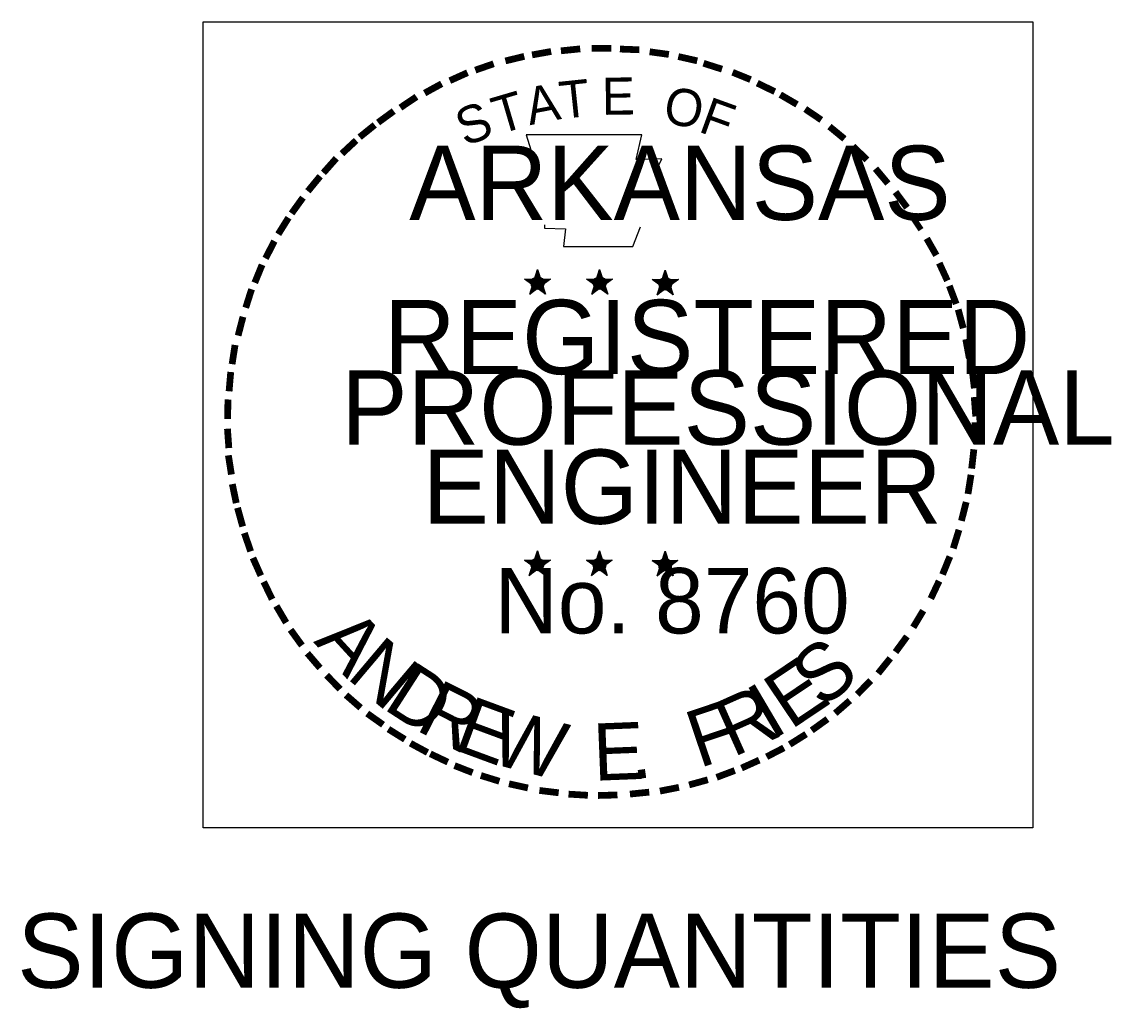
# Model space of a CAD drawing. Extents: x 1226613 to 1228135, y 151309 to 152326.
# Drawn here: x 1227951.4 to 1228134.6, y 151309.4 to 151475.4 of the extents above; entities that cross this region are included whole.
import ezdxf

# ---------------------------------------------------------------- set-up
doc = ezdxf.new("R2010")
doc.units = 0
for name, color, linetype in [('R_Border Notes', 7, 'Continuous'), ('R_Border PE', 7, 'Continuous'), ('R_Border Prem', 7, 'Continuous')]:
    doc.layers.add(name, color=color, linetype=linetype)

msp = doc.modelspace()

# ---------------------------------------------------------------- linework, layer by layer
at = {"layer": 'R_Border PE'}
for p, q in [((1228038.16, 151433.71), (1228037.85, 151432.15)), ((1228038.16, 151433.71), (1228037.91, 151432.09)), ((1228038.16, 151433.71), (1228038.1, 151432.15)), ((1228038.16, 151431.4), (1228038.16, 151433.71)), ((1228038.16, 151433.71), (1228038.6, 151432.09)), ((1228038.16, 151433.71), (1228038.47, 151432.15)), ((1228038.16, 151433.71), (1228038.35, 151432.15)), ((1228048.6, 151433.71), (1228048.28, 151432.15)), ((1228048.6, 151433.71), (1228048.35, 151432.09)), ((1228048.6, 151433.71), (1228048.47, 151432.15)), ((1228048.6, 151431.4), (1228048.6, 151433.71)), ((1228048.6, 151433.71), (1228049.03, 151432.09)), ((1228048.6, 151433.71), (1228048.91, 151432.15)), ((1228048.6, 151433.71), (1228048.72, 151432.15)), ((1228059.66, 151433.59), (1228059.28, 151432.09)), ((1228059.66, 151433.59), (1228059.41, 151432.03)), ((1228059.66, 151433.59), (1228059.53, 151432.03)), ((1228059.66, 151431.34), (1228059.66, 151433.59)), ((1228059.66, 151433.59), (1228060.1, 151432.03)), ((1228059.66, 151433.59), (1228059.97, 151432.03)), ((1228059.66, 151433.59), (1228059.78, 151432.09)), ((1228035.97, 151432.09), (1228038.16, 151431.4)), ((1228035.97, 151432.09), (1228037.6, 151431.96)), ((1228035.97, 151432.09), (1228037.6, 151431.84)), ((1228035.97, 151432.09), (1228037.53, 151431.71)), ((1228035.97, 151432.09), (1228037.53, 151431.46)), ((1228035.97, 151432.09), (1228037.47, 151431.34)), ((1228035.97, 151432.09), (1228037.47, 151431.21)), ((1228036.85, 151429.53), (1228038.16, 151431.4)), ((1228036.85, 151429.53), (1228037.53, 151431.28)), ((1228036.85, 151429.53), (1228037.6, 151431.09)), ((1228036.85, 151429.53), (1228037.72, 151431.03)), ((1228036.85, 151429.53), (1228038.16, 151430.9)), ((1228036.85, 151429.53), (1228037.91, 151430.84)), ((1228036.85, 151429.53), (1228038.22, 151430.71)), ((1228040.35, 151432.09), (1228038.16, 151431.4)), ((1228039.53, 151429.53), (1228038.16, 151431.4)), ((1228039.53, 151429.53), (1228038.16, 151430.9)), ((1228039.53, 151429.53), (1228038.16, 151430.71)), ((1228040.35, 151432.09), (1228038.41, 151431.96)), ((1228039.53, 151429.53), (1228038.41, 151430.84)), ((1228040.35, 151432.09), (1228038.53, 151431.78)), ((1228040.35, 151432.09), (1228038.53, 151431.65)), ((1228039.53, 151429.53), (1228038.6, 151431.09)), ((1228039.53, 151429.53), (1228038.66, 151431.34)), ((1228039.53, 151429.53), (1228038.78, 151431.4)), ((1228040.35, 151432.09), (1228038.97, 151431.53)), ((1228040.35, 151432.09), (1228039.1, 151431.46)), ((1228040.35, 151432.09), (1228039.16, 151431.4)), ((1228046.41, 151432.09), (1228048.6, 151431.4)), ((1228046.41, 151432.09), (1228048.03, 151431.96)), ((1228046.41, 151432.09), (1228048.03, 151431.84)), ((1228046.41, 151432.09), (1228047.97, 151431.71)), ((1228046.41, 151432.09), (1228047.91, 151431.46)), ((1228046.41, 151432.09), (1228047.91, 151431.34)), ((1228046.41, 151432.09), (1228047.91, 151431.21)), ((1228047.28, 151429.53), (1228048.6, 151431.4)), ((1228047.28, 151429.53), (1228047.97, 151431.28)), ((1228047.28, 151429.53), (1228048.03, 151431.09)), ((1228047.28, 151429.53), (1228048.16, 151431.03)), ((1228047.28, 151429.53), (1228048.6, 151430.9)), ((1228047.28, 151429.53), (1228048.35, 151430.84)), ((1228047.28, 151429.53), (1228048.66, 151430.71)), ((1228050.78, 151432.09), (1228048.6, 151431.4)), ((1228049.97, 151429.53), (1228048.6, 151431.4)), ((1228049.97, 151429.53), (1228048.6, 151430.9)), ((1228049.97, 151429.53), (1228048.6, 151430.71)), ((1228050.78, 151432.09), (1228048.85, 151431.96)), ((1228049.97, 151429.53), (1228048.85, 151430.84)), ((1228050.78, 151432.09), (1228048.97, 151431.78)), ((1228050.78, 151432.09), (1228048.97, 151431.65)), ((1228049.97, 151429.53), (1228049.03, 151431.09)), ((1228049.97, 151429.53), (1228049.1, 151431.34)), ((1228049.97, 151429.53), (1228049.22, 151431.4)), ((1228050.78, 151432.09), (1228049.41, 151431.53)), ((1228050.78, 151432.09), (1228049.53, 151431.46)), ((1228050.78, 151432.09), (1228049.6, 151431.4)), ((1228057.47, 151432.03), (1228059.66, 151431.34)), ((1228057.47, 151432.03), (1228059.1, 151431.84)), ((1228057.47, 151432.03), (1228059.03, 151431.71)), ((1228057.47, 151432.03), (1228059.03, 151431.65)), ((1228057.47, 151432.03), (1228058.97, 151431.4)), ((1228057.47, 151432.03), (1228058.97, 151431.28)), ((1228057.47, 151432.03), (1228058.97, 151431.15)), ((1228058.28, 151429.46), (1228059.66, 151431.34)), ((1228058.28, 151429.46), (1228059.03, 151431.21)), ((1228058.28, 151429.46), (1228059.1, 151431.03)), ((1228058.28, 151429.46), (1228059.22, 151430.96)), ((1228058.28, 151429.46), (1228059.66, 151430.84)), ((1228058.28, 151429.46), (1228059.41, 151430.78)), ((1228058.28, 151429.46), (1228059.72, 151430.65)), ((1228061.85, 151432.03), (1228059.66, 151431.34)), ((1228060.97, 151429.46), (1228059.66, 151431.34)), ((1228060.97, 151429.46), (1228059.66, 151430.84)), ((1228060.97, 151429.46), (1228059.66, 151430.65)), ((1228061.85, 151432.03), (1228059.91, 151431.9)), ((1228060.97, 151429.46), (1228059.91, 151430.78)), ((1228061.85, 151432.03), (1228060.03, 151431.71)), ((1228061.85, 151432.03), (1228060.03, 151431.59)), ((1228060.97, 151429.46), (1228060.1, 151431.03)), ((1228060.97, 151429.46), (1228060.16, 151431.28)), ((1228060.97, 151429.46), (1228060.28, 151431.28)), ((1228061.85, 151432.03), (1228060.47, 151431.46)), ((1228061.85, 151432.03), (1228060.53, 151431.4)), ((1228061.85, 151432.03), (1228060.66, 151431.34)), ((1228038.16, 151386.34), (1228037.78, 151384.84)), ((1228038.16, 151386.34), (1228037.91, 151384.78)), ((1228038.16, 151386.34), (1228038.03, 151384.78)), ((1228038.16, 151384.09), (1228038.16, 151386.34)), ((1228038.16, 151386.34), (1228038.6, 151384.78)), ((1228038.16, 151386.34), (1228038.47, 151384.78)), ((1228038.16, 151386.34), (1228038.28, 151384.78)), ((1228048.6, 151386.34), (1228048.22, 151384.84)), ((1228048.6, 151386.34), (1228048.35, 151384.78)), ((1228048.6, 151386.34), (1228048.47, 151384.78)), ((1228048.6, 151384.09), (1228048.6, 151386.34)), ((1228048.6, 151386.34), (1228048.97, 151384.78)), ((1228048.6, 151386.34), (1228048.91, 151384.78)), ((1228048.6, 151386.34), (1228048.72, 151384.78)), ((1228035.97, 151384.78), (1228038.16, 151384.09)), ((1228035.97, 151384.78), (1228037.6, 151384.59)), ((1228035.97, 151384.78), (1228037.53, 151384.46)), ((1228035.97, 151384.78), (1228037.53, 151384.4)), ((1228035.97, 151384.78), (1228037.47, 151384.15)), ((1228035.97, 151384.78), (1228037.47, 151384.03)), ((1228035.97, 151384.78), (1228037.47, 151383.9)), ((1228040.35, 151384.78), (1228038.16, 151384.09)), ((1228040.35, 151384.78), (1228038.41, 151384.65)), ((1228040.35, 151384.78), (1228038.53, 151384.46)), ((1228040.35, 151384.78), (1228038.53, 151384.34)), ((1228040.35, 151384.78), (1228038.91, 151384.21)), ((1228040.35, 151384.78), (1228039.03, 151384.15)), ((1228040.35, 151384.78), (1228039.16, 151384.03)), ((1228046.41, 151384.78), (1228048.6, 151384.09)), ((1228046.41, 151384.78), (1228047.97, 151384.59)), ((1228046.41, 151384.78), (1228047.97, 151384.46)), ((1228046.41, 151384.78), (1228047.97, 151384.4)), ((1228046.41, 151384.78), (1228047.91, 151384.15)), ((1228046.41, 151384.78), (1228047.91, 151384.03)), ((1228046.41, 151384.78), (1228047.91, 151383.9)), ((1228050.72, 151384.78), (1228048.6, 151384.09)), ((1228050.72, 151384.78), (1228048.85, 151384.65)), ((1228050.72, 151384.78), (1228048.97, 151384.46)), ((1228050.72, 151384.78), (1228048.97, 151384.34)), ((1228050.72, 151384.78), (1228049.35, 151384.21)), ((1228050.72, 151384.78), (1228049.47, 151384.15)), ((1228050.72, 151384.78), (1228049.6, 151384.03)), ((1228057.47, 151384.71), (1228059.66, 151384.03)), ((1228057.47, 151384.71), (1228059.03, 151384.53)), ((1228057.47, 151384.71), (1228059.03, 151384.4)), ((1228057.47, 151384.71), (1228058.97, 151384.28)), ((1228057.47, 151384.71), (1228058.97, 151384.09)), ((1228057.47, 151384.71), (1228058.91, 151383.9)), ((1228057.47, 151384.71), (1228058.91, 151383.78)), ((1228059.66, 151386.28), (1228059.28, 151384.71)), ((1228059.66, 151386.28), (1228059.41, 151384.71)), ((1228059.66, 151386.28), (1228059.53, 151384.71)), ((1228059.66, 151384.03), (1228059.66, 151386.28)), ((1228059.66, 151386.28), (1228060.03, 151384.71)), ((1228059.66, 151386.28), (1228059.97, 151384.71)), ((1228059.66, 151386.28), (1228059.78, 151384.71)), ((1228061.78, 151384.71), (1228059.66, 151384.03)), ((1228061.78, 151384.71), (1228059.91, 151384.59)), ((1228061.78, 151384.71), (1228060.03, 151384.4)), ((1228061.78, 151384.71), (1228060.03, 151384.28)), ((1228061.78, 151384.71), (1228060.41, 151384.15)), ((1228061.78, 151384.71), (1228060.53, 151384.03)), ((1228061.78, 151384.71), (1228060.6, 151383.96)), ((1228036.78, 151382.21), (1228038.16, 151384.09)), ((1228036.78, 151382.21), (1228037.53, 151383.96)), ((1228036.78, 151382.21), (1228037.6, 151383.71)), ((1228036.78, 151382.21), (1228037.72, 151383.65)), ((1228036.78, 151382.21), (1228038.16, 151383.59)), ((1228036.78, 151382.21), (1228037.91, 151383.53)), ((1228036.78, 151382.21), (1228038.16, 151383.4)), ((1228039.47, 151382.21), (1228038.1, 151383.4)), ((1228039.47, 151382.21), (1228038.16, 151384.09)), ((1228039.47, 151382.21), (1228038.16, 151383.53)), ((1228039.47, 151382.21), (1228038.35, 151383.53)), ((1228039.47, 151382.21), (1228038.6, 151384.03)), ((1228039.47, 151382.21), (1228038.6, 151383.78)), ((1228039.47, 151382.21), (1228038.78, 151384.03)), ((1228047.22, 151382.21), (1228048.6, 151384.09)), ((1228047.22, 151382.21), (1228047.97, 151383.96)), ((1228047.22, 151382.21), (1228048.03, 151383.71)), ((1228047.22, 151382.21), (1228048.16, 151383.65)), ((1228047.22, 151382.21), (1228048.6, 151383.59)), ((1228047.22, 151382.21), (1228048.35, 151383.53)), ((1228047.22, 151382.21), (1228048.6, 151383.4)), ((1228049.91, 151382.21), (1228048.53, 151383.4)), ((1228049.91, 151382.21), (1228048.6, 151384.09)), ((1228049.91, 151382.21), (1228048.6, 151383.53)), ((1228049.91, 151382.21), (1228048.78, 151383.53)), ((1228049.91, 151382.21), (1228049.03, 151384.03)), ((1228049.91, 151382.21), (1228049.03, 151383.78)), ((1228049.91, 151382.21), (1228049.22, 151384.03)), ((1228058.28, 151382.15), (1228059.66, 151384.03)), ((1228058.28, 151382.15), (1228058.97, 151383.9)), ((1228058.28, 151382.15), (1228059.03, 151383.65)), ((1228058.28, 151382.15), (1228059.22, 151383.59)), ((1228058.28, 151382.15), (1228059.41, 151383.46)), ((1228058.28, 151382.15), (1228059.6, 151383.46)), ((1228058.28, 151382.15), (1228059.66, 151383.34)), ((1228060.97, 151382.15), (1228059.6, 151383.46)), ((1228060.97, 151382.15), (1228059.6, 151383.28)), ((1228060.97, 151382.15), (1228059.66, 151384.03)), ((1228060.97, 151382.15), (1228059.85, 151383.46)), ((1228060.97, 151382.15), (1228060.03, 151383.65)), ((1228060.97, 151382.15), (1228060.1, 151383.96)), ((1228060.97, 151382.15), (1228060.22, 151383.96))]:
    msp.add_line(p, q, dxfattribs=at)
for points in [[(1228036.28, 151456.34), (1228037.91, 151451.15)], [(1228058.22, 151450.59), (1228059.1, 151452.34), (1228054.78, 151452.21), (1228055.72, 151456.34), (1228036.28, 151456.34)], [(1228039.35, 151441.21), (1228039.35, 151440.65), (1228042.85, 151440.53), (1228042.53, 151437.59), (1228054.22, 151437.59), (1228055.47, 151440.9)], [(1228038.16, 151433.71), (1228039.53, 151429.53), (1228035.97, 151432.09), (1228040.35, 151432.09), (1228036.85, 151429.53), (1228038.16, 151433.71)], [(1228048.6, 151433.71), (1228049.97, 151429.53), (1228046.41, 151432.09), (1228050.78, 151432.09), (1228047.28, 151429.53), (1228048.6, 151433.71)], [(1228059.66, 151433.59), (1228060.97, 151429.46), (1228057.47, 151432.03), (1228061.85, 151432.03), (1228058.28, 151429.46), (1228059.66, 151433.59)], [(1228038.16, 151386.34), (1228039.47, 151382.21), (1228035.97, 151384.78), (1228040.35, 151384.78), (1228036.78, 151382.21), (1228038.16, 151386.34)], [(1228048.6, 151386.34), (1228049.91, 151382.21), (1228046.41, 151384.78), (1228050.72, 151384.78), (1228047.22, 151382.21), (1228048.6, 151386.34)], [(1228059.66, 151386.28), (1228060.97, 151382.15), (1228057.47, 151384.71), (1228061.78, 151384.71), (1228058.28, 151382.15), (1228059.66, 151386.28)]]:
    msp.add_lwpolyline(points, dxfattribs=at)
for centre, radius in [((1228038.18, 151431.4), 1.08), ((1228038.18, 151431.4), 0.975), ((1228038.18, 151431.4), 0.904), ((1228038.18, 151431.4), 0.83), ((1228038.18, 151431.4), 0.723), ((1228048.61, 151431.4), 1.08), ((1228048.61, 151431.4), 0.975), ((1228048.61, 151431.4), 0.904), ((1228048.61, 151431.4), 0.83), ((1228048.61, 151431.4), 0.723), ((1228059.65, 151431.32), 1.08), ((1228059.65, 151431.32), 0.975), ((1228059.65, 151431.32), 0.904), ((1228059.65, 151431.32), 0.83), ((1228038.18, 151431.4), 0.672), ((1228038.18, 151431.4), 0.619), ((1228038.18, 151431.4), 0.533), ((1228038.18, 151431.4), 0.467), ((1228038.18, 151431.4), 0.388), ((1228038.18, 151431.4), 0.31), ((1228038.18, 151431.4), 0.231), ((1228038.18, 151431.4), 0.185), ((1228038.18, 151431.4), 0.0901), ((1228048.61, 151431.4), 0.672), ((1228048.61, 151431.4), 0.619), ((1228048.61, 151431.4), 0.533), ((1228048.61, 151431.4), 0.467), ((1228048.61, 151431.4), 0.388), ((1228048.61, 151431.4), 0.31), ((1228048.61, 151431.4), 0.231), ((1228048.61, 151431.4), 0.185), ((1228048.61, 151431.4), 0.0901), ((1228059.65, 151431.32), 0.723), ((1228059.65, 151431.32), 0.672), ((1228059.65, 151431.32), 0.619), ((1228059.65, 151431.32), 0.533), ((1228059.65, 151431.32), 0.467), ((1228059.65, 151431.32), 0.388), ((1228059.65, 151431.32), 0.31), ((1228059.65, 151431.32), 0.231), ((1228059.65, 151431.32), 0.185), ((1228059.65, 151431.32), 0.0901), ((1228038.15, 151384.06), 1.08), ((1228038.15, 151384.06), 0.975), ((1228038.15, 151384.06), 0.904), ((1228038.15, 151384.06), 0.83), ((1228038.15, 151384.06), 0.723), ((1228038.15, 151384.06), 0.672), ((1228038.15, 151384.06), 0.619), ((1228038.15, 151384.06), 0.533), ((1228038.15, 151384.06), 0.467), ((1228048.58, 151384.06), 1.08), ((1228048.58, 151384.06), 0.975), ((1228048.58, 151384.06), 0.904), ((1228048.58, 151384.06), 0.83), ((1228048.58, 151384.06), 0.723), ((1228048.58, 151384.06), 0.672), ((1228048.58, 151384.06), 0.619), ((1228048.58, 151384.06), 0.533), ((1228048.58, 151384.06), 0.467), ((1228059.63, 151383.99), 1.08), ((1228059.63, 151383.99), 0.975), ((1228059.63, 151383.99), 0.904), ((1228059.63, 151383.99), 0.83), ((1228059.63, 151383.99), 0.723), ((1228059.63, 151383.99), 0.672), ((1228059.63, 151383.99), 0.619), ((1228059.63, 151383.99), 0.533), ((1228038.15, 151384.06), 0.388), ((1228038.15, 151384.06), 0.31), ((1228038.15, 151384.06), 0.231), ((1228038.15, 151384.06), 0.185), ((1228038.15, 151384.06), 0.0901), ((1228048.58, 151384.06), 0.388), ((1228048.58, 151384.06), 0.31), ((1228048.58, 151384.06), 0.231), ((1228048.58, 151384.06), 0.185), ((1228048.58, 151384.06), 0.0901), ((1228059.63, 151383.99), 0.467), ((1228059.63, 151383.99), 0.388), ((1228059.63, 151383.99), 0.31), ((1228059.63, 151383.99), 0.231), ((1228059.63, 151383.99), 0.185), ((1228059.63, 151383.99), 0.0901)]:
    msp.add_circle(centre, radius, dxfattribs=at)
at = {"layer": 'R_Border Prem'}
msp.add_lwpolyline([(1227981.94, 151475.38), (1228121.44, 151475.38), (1228121.44, 151339.76), (1227981.94, 151339.76)], close=True, dxfattribs=at)

# ---------------------------------------------------------------- texts
at = {"layer": 'R_Border Notes'}
msp.add_text('SIGNING QUANTITIES', height=12.5, dxfattribs=at).set_placement((1227950.68, 151312.82))
at = {"layer": 'R_Border PE'}
for s, height, rotation, p in [('-', 10, 10.2193, (1228037.35, 151465.9)), ('-', 10, 5.8968, (1228041.91, 151466.59)), ('-', 10, 0.1862, (1228046.72, 151467.03)), ('-', 10, 357.743, (1228051.28, 151466.96)), ('-', 10, 352.1617, (1228055.91, 151466.59)), ('-', 10, 19.1761, (1228028.41, 151463.4)), ('-', 10, 13.6302, (1228033.1, 151464.9)), ('-', 10, 347.2049, (1228060.41, 151465.9)), ('-', 10, 342.3362, (1228064.35, 151464.9)), ('-', 10, 24.3072, (1228024.47, 151461.71)), ('-', 10, 337.8551, (1228068.97, 151463.53)), ('-', 10, 28.7918, (1228020.53, 151459.71)), ('T', 6.25, 6.0228, (1228042.16, 151459.03)), ('E', 6.25, 0.8323, (1228049.03, 151459.71)), ('-', 10, 334.1211, (1228072.91, 151461.84)), ('T', 6.25, 16.4036, (1228031.66, 151456.4)), ('A', 6.25, 11.2132, (1228036.85, 151457.96)), ('O', 6.25, 350.4515, (1228059.1, 151458.4)), ('-', 10, 329.6409, (1228076.53, 151460.09)), ('-', 10, 34.0636, (1228016.78, 151457.4)), ('S', 6.25, 21.594, (1228025.97, 151454.34)), ('F', 6.25, 340.0707, (1228065.03, 151456.96)), ('-', 10, 36.2317, (1228013.16, 151454.96)), ('-', 10, 325.8627, (1228080.53, 151457.84)), ('-', 10, 38.9507, (1228010.22, 151452.59)), ('-', 10, 320.5297, (1228084.35, 151455.15)), ('-', 10, 42.9622, (1228007.47, 151449.96)), ('-', 10, 315.5786, (1228088.1, 151452.09)), ('-', 10, 48.423, (1228004.66, 151446.96)), ('-', 10, 309.8797, (1228091.66, 151448.65)), ('-', 10, 50.6142, (1228002.16, 151443.96)), ('-', 10, 306.6522, (1228094.91, 151444.9)), ('-', 10, 54.2325, (1227999.6, 151440.4)), ('-', 10, 58.0706, (1227997.53, 151437.09)), ('-', 8.75, 303.6753, (1228097.97, 151441.34)), ('-', 10, 62.8713, (1227995.6, 151433.28)), ('-', 10, 299.6684, (1228099.97, 151437.53)), ('-', 10, 67.7743, (1227993.97, 151429.46)), ('-', 10, 294.6628, (1228101.97, 151433.71)), ('-', 10, 72.3945, (1227992.6, 151425.53)), ('-', 10, 290.5728, (1228103.6, 151430.15)), ('-', 10, 285.1233, (1228105.03, 151426.53)), ('-', 10, 75.461, (1227991.41, 151421.03)), ('-', 10, 280.5493, (1228106.28, 151421.84)), ('-', 10, 81.2013, (1227990.53, 151416.59)), ('-', 10, 85.1863, (1227990.1, 151412.28)), ('-', 10, 276.5962, (1228107.35, 151417.09)), ('-', 10, 274.3301, (1228107.72, 151412.53)), ('-', 10, 89.0622, (1227989.91, 151407.9)), ('-', 10, 94.1959, (1227990.16, 151403.34)), ('-', 10, 269.9407, (1228107.91, 151408.59)), ('-', 10, 263.5172, (1228107.78, 151404.46)), ('-', 10, 98.9479, (1227990.6, 151399.21)), ('-', 10, 260.9953, (1228107.35, 151400.34)), ('-', 10, 101.7149, (1227991.41, 151394.59)), ('-', 10, 105.4578, (1227992.47, 151390.9)), ('-', 10, 255.7626, (1228106.66, 151396.09)), ('-', 10, 252.8681, (1228105.53, 151391.59)), ('-', 10, 109.0874, (1227993.78, 151386.96)), ('-', 10, 114.0643, (1227995.41, 151383.21)), ('-', 10, 247.8887, (1228104.16, 151387.4)), ('-', 10, 115.7289, (1227997.28, 151379.34)), ('-', 10, 244.6197, (1228102.47, 151383.46)), ('-', 10, 120.4471, (1227999.53, 151375.71)), ('-', 10, 239.0712, (1228100.03, 151378.78)), ('A', 9.62, 312.4727, (1228000.41, 151371.02)), ('-', 10, 125.8934, (1228002.03, 151372.21)), ('N', 9.62, 319.8362, (1228005.84, 151365.09)), ('-', 10, 233.8452, (1228097.53, 151374.71)), ('S', 9.62, 39.723, (1228086.07, 151359.62)), ('-', 10, 130.7181, (1228004.91, 151368.71)), ('E', 9.62, 33.8878, (1228080.73, 151356.14)), ('-', 10, 231.2538, (1228094.85, 151371.15)), ('D', 9.62, 327.1996, (1228011.99, 151359.9)), ('-', 10, 134.2238, (1228008.16, 151365.34)), ('R', 9.62, 333.1738, (1228017.43, 151356.3)), ('-', 10, 225.7653, (1228091.85, 151367.65)), ('-', 10, 138.9338, (1228011.41, 151362.46)), ('R', 9.62, 24.0235, (1228071, 151351.54)), ('I', 9.62, 30.5534, (1228077.53, 151354.4)), ('E', 9.62, 339.7037, (1228023.77, 151353.03)), ('F', 9.62, 18.6051, (1228065.35, 151349.74)), ('-', 10, 221.0851, (1228088.6, 151364.46)), ('-', 10, 144.6463, (1228014.91, 151359.9)), ('W', 9.62, 345.5389, (1228029.72, 151350.74)), ('E', 9.62, 2.2804, (1228047.69, 151347.65)), ('-', 10, 215.7363, (1228085.16, 151361.53)), ('-', 10, 148.0898, (1228018.41, 151357.59)), ('-', 10, 212.2491, (1228081.78, 151359.09)), ('-', 10, 151.5704, (1228022.03, 151355.53)), ('-', 10, 207.3568, (1228078.35, 151356.9)), ('-', 10, 154.6002, (1228025.28, 151354.03)), ('-', 10, 204.2516, (1228074.41, 151354.9)), ('-', 10, 158.5612, (1228029.22, 151352.4)), ('-', 10, 200.7184, (1228070.53, 151353.21)), ('-', 10, 162.7983, (1228033.47, 151351.09)), ('.', 9.62, 8.1156, (1228054.07, 151347.82)), ('-', 10, 195.4743, (1228066.35, 151351.71)), ('-', 10, 167.5555, (1228037.97, 151350.09)), ('-', 10, 173.1155, (1228042.78, 151349.4)), ('-', 10, 185.8167, (1228057.16, 151349.65)), ('-', 10, 191.2858, (1228061.78, 151350.46)), ('-', 10, 176.5183, (1228047.47, 151349.03)), ('-', 10, 181.5918, (1228052.1, 151349.15))]:
    msp.add_text(s, height=height, rotation=rotation, dxfattribs=at).set_placement(p)
for s, height, p in [('ARKANSAS', 12.5, (1228016.6, 151442.03)), ('REGISTERED', 12.5, (1228012.35, 151416.09)), ('PROFESSIONAL', 12.4999, (1228005.16, 151404.21)), ('ENGINEER', 12.5, (1228018.85, 151390.9)), ('No. 8760', 11, (1228030.96, 151372.46))]:
    msp.add_text(s, height=height, dxfattribs=at).set_placement(p)

doc.saveas('drawing.dxf')
